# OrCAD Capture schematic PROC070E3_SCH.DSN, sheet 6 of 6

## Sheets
6 05. LCD_POWER: size C; title: LCD POWER
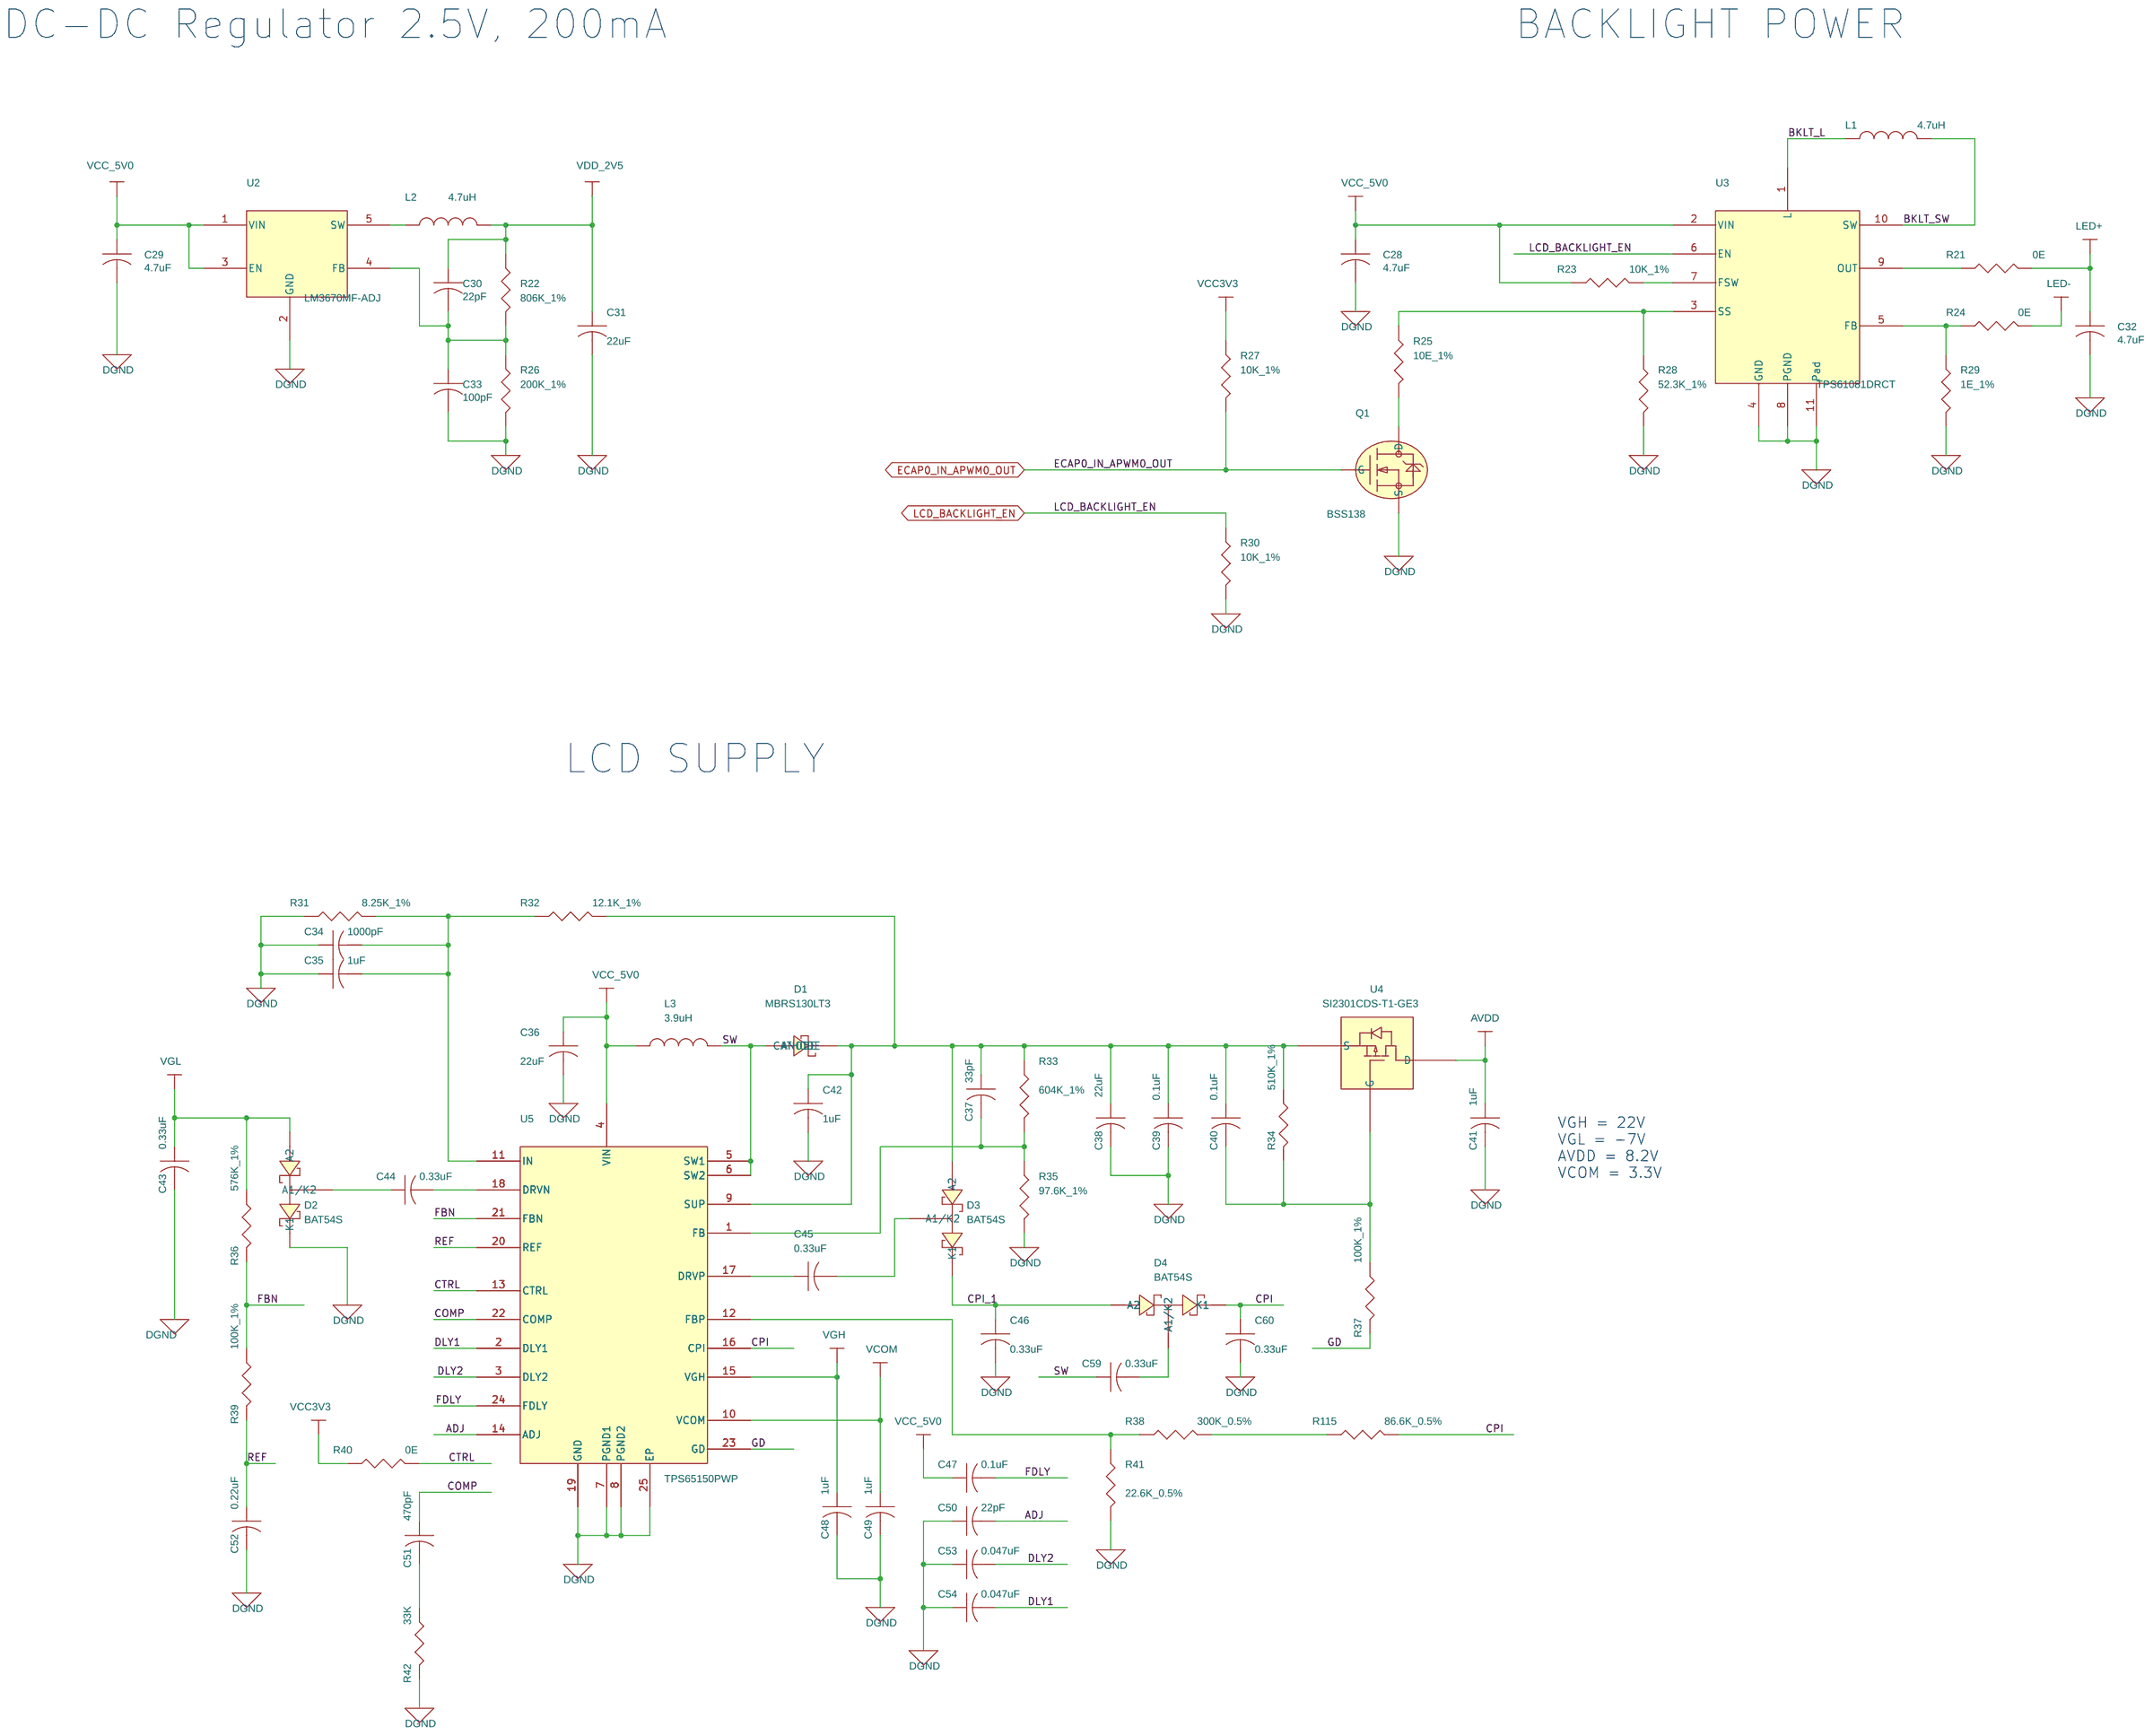
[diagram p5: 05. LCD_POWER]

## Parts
C28  4.7uF  [CAP0402_0-75]
C29  4.7uF  [CAP0402_0-75]
C30  22pF  [CAP0402_0-75]
C31  22uF  [CAP0805_1]
C32  4.7uF  [CAP0805_1-5]
C33  100pF  [CAP0402]
C34  1000pF  [CAP0402_0-75]
C35  1uF  [CAP0402_0-75]
C36  22uF  [CAP0805_1]
C37  33pF  [CAP0402]
C38  22uF  [CAP0805_1]
C39  0.1uF  [CAP0201_0-5]
C40  0.1uF  [CAP0201_0-5]
C41  1uF  [CAP0805_1-5]
C42  1uF  [CAP0805_1-5]
C43  0.33uF  [CAP0603]
C44  0.33uF  [CAP0603]
C45  0.33uF  [CAP0603]
C46  0.33uF  [CAP0603]
C47  0.1uF  [CAP0201_0-5]
C48  1uF  [CAP0805_1-5]
C49  1uF  [CAP0402_0-75]
C50  22pF  [CAP0402_0-75]
C51  470pF  [CAP0402_0-75]
C52  0.22uF  [CAP0603]
C53  0.047uF  [CAP0402]
C54  0.047uF  [CAP0402]
C59  0.33uF  [CAP0603]
C60  0.33uF  [CAP0603]
D1  MBRS130LT3  [DIO_SMB]
D2  BAT54S  [DIO_SOT23_123]
D3  BAT54S  [DIO_SOT23_123]
D4  BAT54S  [DIO_SOT23_123]
L1  4.7uH  [IND_VLCF5020T_205X210_SMD]
L2  4.7uH  [IND_LQH32PN_140X110_SMD_1-7]
L3  3.9uH  [IND_ELL4GG_170X170_SMD]
Q1  BSS138  [TO_SOT23-123]
R21  0E  [RES0402_0-5]
R22  806K_1%  [RES0402]
R23  10K_1%  [RES0402_0-5]
R24  0E  [RES0402_0-5]
R25  10E_1%  [RES0402_0-5]
R26  200K_1%  [RES0402]
R27  10K_1%  [RES0402_0-5]
R28  52.3K_1%  [RES0201_0-5]
R29  1E_1%  [RES0402]
R30  10K_1%  [RES0402_0-5]
R31  8.25K_1%  [RES0402]
R32  12.1K_1%  [RES0402]
R33  604K_1%  [RES0603]
R34  510K_1%  [RES0402]
R35  97.6K_1%  [RES0402_0-5]
R36  576K_1%  [RES0603]
R37  100K_1%  [RES0402_0-5]
R38  300K_0.5%  [RES0603_0-75]
R39  100K_1%  [RES0402_0-5]
R40  0E  [RES0402_0-5]
R41  22.6K_0.5%  [RES0603_0-75]
R42  33K  [RES0402]
R115  86.6K_0.5%  [RES0603_0-75]
U2  LM3670MF-ADJ  [SOT23-5_1-5]
U3  TPS61081DRCT  [SON10_19-68_125X125]
U4  SI2301CDS-T1-GE3  [SOT23-123]
U5  TPS65150PWP  [HTSSOP24_TPS65150_180X310_1-2]

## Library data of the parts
C28 C29 = CAP: CAP CERAMIC 4.7uF 10V 10% X5R 0402; Chkd/date: MANIRAJA/050517; Crtd /date: MANIRAJA/050517; Custom_Duty: 15%; Customs_HS_Code: 85322990; Distributor_name: DIGIKEY; Distributor_part_number: 311-3477-1-ND; Height: 0.65MM; Mfr_name: YAGEO AMERICA; Mfr_part_number: CC0402KRX5R6BB475; Mistral Part No: 120014080006-R; Package: 0402; Part_type: CAPACITORS\CERAMIC; Project: GOLDEN-I LITE; RoHS: RoHS; Temperature: -55°C+85°C; Tolerance: 10%; Voltage: 10V; Wattage: NA; Weight: NA; Datasheet: Y:\MIS_DATABASE\DATASHEETS\CAPACITORS\YACC-X5R.PDF
C30 C50 = CAP: CAP CERAMIC 22pF 25V 5% NP0 0402; Chkd/date: VASANTHA/060117; Crtd /date: MAZHAR/040505; Custom_Duty: 15%; Customs_HS_Code: 85322990; Distributor_name: DIGIKEY; Distributor_part_number: 478-6192-2-ND; Height: 0.56MM; Mfr_name: AVX CORPORATION; Mfr_part_number: 04023A220JAT2A; Mistral Part No: 120009030322-R; Package: 0402; Part_type: CAPACITORS\CERAMIC; Project: TELEMATICS-02; RoHS: RoHS; Temperature: -55°C+125°C; Tolerance: 5%; Voltage: 25V; Wattage: NA; Weight: 0.65mg; Datasheet: Y:\MIS_DATABASE\DATASHEETS\CAPACITORS\AVX_MLC.PDF
C31 C36 C38 = CAP: CAP CERAMIC 22uF 16V 20% X5R 0805; Chkd/date: VASANTHA/220218; Crtd /date: ALVY/220218; Custom_Duty: 15%; Customs_HS_Code: 85322990; Distributor_name: DIGIKEY; Distributor_part_number: 1276-6780-1-ND; Footprint Path: Y:\MIS_DATABASE\Library\ALTIUM_TOOL\PCB_FOOTPRINTS\Altium_Footprint_Lib.PcbLib; Height: 0.95MM; Library Path: Y:\MIS_DATABASE\Library\ALTIUM_TOOL\SCHEMATICS_PARTS\MS_DISCRETE_Library.schlib; Mfr_name: SAMSUNG ELECTRO MECHANIC; Mfr_part_number: CL21A226MOCLRNC; Mistral Part No: 120018020013-R; Package: 0805; Part_type: CAPACITORS\CERAMIC; Project: 820TABPOC_CB; RoHS: RoHS; Temperature: -55°C+85°C; Tolerance: 20%; Voltage: 16V; Wattage: NA; Weight: NA; Datasheet: Y:\MIS_DATABASE\DATASHEETS\CAPACITORS\CL_SERIES.PDF
C32 = CAP: CAP CERAMIC 4.7uF 50V 20% X5R 0805; Chkd/date: VASANTHA/200614; Crtd /date: MANIRAJA/210317; Custom_Duty: 15%; Customs_HS_Code: 85322990; Distributor_name: DIGIKEY; Distributor_part_number: 445-5981-1-ND; Height: 1.45MM; Mfr_name: TDK CORPORATION; Mfr_part_number: C2012X5R1H475M125AB; Mistral Part No: 120014060013-R; Package: 0805; Part_type: CAPACITORS\CERAMIC; Project: AEGIS_POM; RoHS: RoHS; Temperature: -55°C+85°C; Tolerance: 20%; Voltage: 50V; Wattage: NA; Weight: 5.5mg; Datasheet: Y:\MIS_DATABASE\DATASHEETS\CAPACITORS\C2012X5R.PDF
C33 = CAP: CAP CERAMIC 100pF 25V 10% NP0 0402; Chkd/date: NAVEED/070814; Crtd /date: VASANTHA/300714; Custom_Duty: 15%; Customs_HS_Code: 85322990; Distributor_name: DIGIKEY; Distributor_part_number: 399-7748-1-ND; Height: 0.55MM; Mfr_name: KEMET; Mfr_part_number: C0402C101K3GACTU; Mistral Part No: 120014070037-R; Package: 0402; Part_type: CAPACITORS\CERAMIC; Project: AEGIS_POM; RoHS: RoHS; Temperature: NA; Tolerance: 10%; Voltage: 25V; Wattage: NA; Weight: NA; Datasheet: Y:\MIS_DATABASE\DATASHEETS\CAPACITORS\KEMET-C08.PDF
C34 = CAP: CAP CERAMIC 1000pF 25V 10% X7R 0402; Chkd/date: VASANTHA/191216; Crtd /date: MAZHAR/050307; Custom_Duty: 15%; Customs_HS_Code: 85322990; Distributor_name: DIGIKEY; Distributor_part_number: 399-1031-1-ND; Height: 0.55MM; Mfr_name: KEMET; Mfr_part_number: C0402C102K3RACTU; Mistral Part No: 120009030145-R; Package: 0402; Part_type: CAPACITORS\CERAMIC; Project: LTS; RoHS: RoHS; Temperature: -55°C+125°C; Tolerance: 10%; Voltage: 25V; Wattage: NA; Weight: 0.65mg; Datasheet: Y:\MIS_DATABASE\DATASHEETS\CAPACITORS\KEMET-C08.PDF
C35 C49 = CAP: CAP CERAMIC 1uF 16V 10% X5R 0402; Chkd/date: MANIRAJA/210817; Crtd /date: MANIRAJA/210817; Custom_Duty: 15%; Customs_HS_Code: 85322990; Distributor_name: DIGIKEY; Distributor_part_number: 587-3709-1-ND; Height: 0.55MM; Mfr_name: TAIYO YUDEN; Mfr_part_number: EMK105BJ105KVHF; Mistral Part No: 120011050002-R; Package: 0402; Part_type: CAPACITORS\CERAMIC; Project: TI_RF_DC CARD; RoHS: RoHS; Temperature: -55°C+85°C; Tolerance: 10%; Voltage: 16V; Wattage: NA; Weight: 0.65mg; Datasheet: Y:\MIS_DATABASE\DATASHEETS\CAPACITORS\EMK105BJ105KVHF.PDF
C37 = CAP: CAP CERAMIC 33pF 16V 1% NP0 0402; Chkd/date: MAZHAR/241208; Crtd /date: USMAN/150908; Custom_Duty: 15%; Customs_HS_Code: 85322990; Distributor_name: DIGIKEY; Distributor_part_number: 0402YA330FAT2A-ND; Height: 0.60MM; Mfr_name: AVX CORPORATION; Mfr_part_number: 0402YA330FAT2A; Mistral Part No: 120009030388-R; Package: 0402; Part_type: CAPACITORS\CERAMIC; Project: MDC; RoHS: RoHS; Tolerance: 1%; Voltage: 16V; Datasheet: Y:\MIS_DATABASE\DATASHEETS\CAPACITORS\AVX_MLC.PDF
C39 C40 C47 = CAP: CAP CERAMIC 0.1uF 16V 10% X5R 0201; Chkd/date: VASANTHA/140217; Crtd /date: MANIRAJA/140217; Custom_Duty: 15%; Customs_HS_Code: 85322990; Distributor_name: DIGIKEY; Distributor_part_number: 311-1597-1-ND; Height: 0.33MM; Mfr_name: YAGEO AMERICA; Mfr_part_number: CC0201KRX5R7BB104; Mistral Part No: 120009030072-R; Package: 0201; Part_type: CAPACITORS\CERAMIC; Project: GOLDEN-I LITE; RoHS: RoHS; Temperature: -55°C+85°C; Tolerance: 10%; Voltage: 16V; Wattage: NA; Weight: 0.17mg; Datasheet: Y:\MIS_DATABASE\DATASHEETS\CAPACITORS\CC-SERIES.PDF
C41 C42 C48 = CAP: CAP CERAMIC 1uF 50V 10% X7R 0805; Chkd/date: MANIRAJA/130617; Crtd /date: MAZHAR/190111; Custom_Duty: 15%; Customs_HS_Code: 85322990; Distributor_name: DIGIKEY; Distributor_part_number: 490-4736-1-ND; Height: 1.35MM; Mfr_name: MURATA; Mfr_part_number: GRM21BR71H105KA12L; Mistral Part No: 120011010018-R; Package: 0805; Part_type: CAPACITORS\CERAMIC; Project: ITS-PWR_CARD; RoHS: RoHS; Temperature: -55°C+125°C; Tolerance: 10%; Voltage: 50V; Wattage: NA; Weight: 6mg; Datasheet: Y:\MIS_DATABASE\DATASHEETS\CAPACITORS\GRM21BR71H105KA12.PDF
C43-C46 C59 C60 = CAP: CAP CERAMIC 0.33uF 50V 20% X5R 0603; Chkd/date: BAVISH/111011; Crtd /date: CHAITHANYA/111011; Custom_Duty: 15%; Customs_HS_Code: 85322990; Distributor_name: DIGIKEY; Distributor_part_number: 445-7463-1-ND; Height: 0.90MM; Mfr_name: TDK CORPORATION; Mfr_part_number: C1608X5R1H334M; Mistral Part No: 120011100028-R; Package: 0603; Part_type: CAPACITORS\CERAMIC; Project: VIDEO-GADGET; RoHS: RoHS; Temperature: -55°C+85°C; Tolerance: 20%; Voltage: 50V; Wattage: NA; Weight: NA; Datasheet: Y:\MIS_DATABASE\DATASHEETS\CAPACITORS\TDK_CAP.PDF
C51 = CAP: CAP CERAMIC 470pF 25V 10% X7R 0402; Chkd/date: VASANTHA/281216; Crtd /date: CHAITHANYA/071111; Custom_Duty: 15%; Customs_HS_Code: 85322990; Distributor_name: DIGIKEY; Distributor_part_number: PCC471BQCT-ND; Height: 0.55MM; Mfr_name: PANASONIC-ECG; Mfr_part_number: ECJ-0EB1E471K; Mistral Part No: 120011110003-R; Package: 0402; Part_type: CAPACITORS\CERAMIC; Project: NA10NG; RoHS: RoHS; Temperature: -55°C+125°C; Tolerance: 10%; Voltage: 25V; Wattage: NA; Weight: 0.8mg; Datasheet: Y:\MIS_DATABASE\DATASHEETS\CAPACITORS\PAN-ECJ.PDF
C52 = CAP: CAP CERAMIC 0.22uF 25V 10% X7R 0603; Chkd/date: MAZHAR/291110; Crtd /date: BAVISH/291110; Custom_Duty: 15%; Customs_HS_Code: 85322990; Distributor_name: DIGIKEY; Distributor_part_number: 445-5191-1-ND; Height: 0.90MM; Mfr_name: TDK CORPORATION; Mfr_part_number: C1608X7R1E224K; Mistral Part No: 120010110026-R; Package: 0603; Part_type: CAPACITORS\CERAMIC; Project: EM-FLS; RoHS: RoHS; Temperature: -55°C+125°C; Tolerance: 5%; Voltage: 25V; Wattage: NA; Weight: NA; Datasheet: Y:\MIS_DATABASE\DATASHEETS\CAPACITORS\C1608.PDF
C53 C54 = CAP: CAP CERAMIC 0.047uF 25V 10% X7R 0402; Chkd/date: MAZHAR/041208; Crtd /date: USMAN/011208; Custom_Duty: 15%; Customs_HS_Code: 85322990; Distributor_name: DIGIKEY; Distributor_part_number: 490-3254-1-ND; Height: 0.55MM; Mfr_name: MURATA; Mfr_part_number: GRM155R71E473KA88D; Mistral Part No: 120009030046; Package: 0402; Part_type: CAPACITORS\CERAMIC; Project: PICO PROJECTOR; Tolerance: 10%; Voltage: 25V; Datasheet: Y:\MIS_DATABASE\DATASHEETS\CAPACITORS\GRM188SERIES.PDF
D1 = DIODE_SCHOTTKY: DIODE SCHOTTKY 30V 1A SMB; Alternate_mfr_name_A: ON SEMICONDUCTOR; Alternate_mfr_part_number_A: MBRS130LT3G; Chkd/date: SHREESHAIL/191205; Crtd /date: MAZHAR/020505; Custom_Duty: 15%; Customs_HS_Code: 85412900; Distributor_name: DIGIKEY; Distributor_part_number: MBRS130LT3OSCT-ND; Height: 2.56MM; Mfr_name: ON SEMICONDUCTOR; Mistral Part No: 130009030214; Package: SMB; Part_type: DIODE\SCHOTTKY; Project: HSWD; Voltage: 30V; Datasheet: Y:\MIS_DATABASE\DATASHEETS\DISCRETES\DIODES\MBRS130LT3-D.PDF
D2-D4 = DIODE_BAT54S_SOT23-123: DIODE SCHOTTKY 30V 200mA SOT23-3; Chkd/date: SHREESHAIL/191205; Crtd /date: MAZHAR/270405; Custom_Duty: 15%; Customs_HS_Code: 85412900; Distributor_name: DIGIKEY; Distributor_part_number: BAT54SFSCT-ND; Height: 1.15MM; Mfr_name: FAIRCHILD; Mistral Part No: 130009030192; Package: SOT23-3; Part_type: DIODE\SCHOTTKY; Project: RAINIER-3; Voltage: 30V; Datasheet: Y:\MIS_DATABASE\DATASHEETS\DISCRETES\DIODES\BAT54C.PDF
L1 = INDUCTOR: IND POWER 4.7uH 1.7A 30% SMD; Chkd/date: VASANTHA/230714; Crtd /date: BAVISH/120511; Custom_Duty: 24%; Customs_HS_Code: 85437099; Distributor_name: DIGIKEY; Distributor_part_number: 445-3207-1-ND; Height: 2.00MM; Mfr_name: TDK CORPORATION; Mfr_part_number: VLCF5020T-4R7N1R7-1; Mistral Part No: 130011050012-R; Package: SMD; Project: CENTAURUS_LCD-ADAPTER; RoHS: RoHS; Temperature: -40°C+105°C; Tolerance: 30%; Voltage: NA; Wattage: NA; Weight: NA; Datasheet: Y:\MIS_DATABASE\DATASHEETS\DISCRETES\INDUCTORS\VLCF5020T.PDF
L2 = INDUCTOR: IND POWER 4.7uH 1000mA 30% SMD; Chkd/date: MANIRAJA/300517; Crtd /date: MUDDU/080310; Custom_Duty: 24%; Customs_HS_Code: 85437099; Distributor_name: DIGIKEY; Distributor_part_number: 490-5338-1-ND; Height: 1.70MM; Mfr_name: MURATA; Mfr_part_number: LQH32PN4R7NN0L; Mistral Part No: 130010030011-R; Package: SMD; Project: VME_DSP_SUITE; RoHS: RoHS; Temperature: -40°C+85°C; Tolerance: 30%; Voltage: NA; Wattage: NA; Weight: NA; Datasheet: Y:\MIS_DATABASE\DATASHEETS\DISCRETES\INDUCTORS\LQH32PN.PDF
L3 = INDUCTOR: IND CHOKE 3.9uH 30% SMD; Chkd/date: VASANTHA/170215; Crtd /date: JEBRAN/160115; Custom_Duty: 24%; Customs_HS_Code: 85437099; Distributor_name: DIGIKEY; Distributor_part_number: PCD2201CT-ND; Height: 1.40MM; Mfr_name: PANASONIC; Mfr_part_number: ELL-4GG3R9N; Mistral Part No: 130015010034-R; Package: SMD; Project: ZK BIOMETRIC; RoHS: RoHS; Temperature: -40°C+85°C; Tolerance: 30%; Voltage: NA; Wattage: NA; Weight: NA; Datasheet: Y:\MIS_DATABASE\DATASHEETS\DISCRETES\INDUCTORS\ELL4GG.PDF
Q1 = MOSFET_BSS138: IC MOSFET N-CHANNEL 50V 200mA SOT23-3; Chkd/date: SUHAS/191010; Crtd /date: USMAN/240709; Custom_Duty: 15%; Customs_HS_Code: 85423100; Distributor_name: DIGIKEY; Distributor_part_number: BSS138CT-ND; Height: 1.20MM; Mfr_name: DIODES INC; Mfr_part_number: BSS138-7-F; Mistral Part No: 142009070019-R; Package: SOT23-3; Part_type: ICS\POWER\MOSFET; Project: KHAN_MAIN; RoHS: RoHS; Temperature: -55°C+150°C; Voltage: 50V; Wattage: 300mW; Weight: 0.008g; Datasheet: Y:\MIS_DATABASE\DATASHEETS\DISCRETES\TRANSISTORS_FETS\BSS138.PDF
R21 R24 R40 = RESISTOR: RES 0E 1/16W 0402; Chkd/date: VASANTHA/201216; Crtd /date: MUDDU/190810; Custom_Duty: 15%; Customs_HS_Code: 85332119; Distributor_name: DIGIKEY; Distributor_part_number: 541-0.0JCT-ND; Footprint Path: Y:\MIS_DATABASE\Library\ALTIUM_TOOL\PCB_FOOTPRINTS\Altium_Footprint_Lib.PcbLib; Height: 0.40MM; Library Path: Y:\MIS_DATABASE\Library\ALTIUM_TOOL\SCHEMATICS_PARTS\MS_DISCRETE_Library.schlib; Mfr_name: VISHAY; Mfr_part_number: CRCW04020000Z0ED; Mistral Part No: 110010080019-P; Package: 0402; Part_type: RESISTORS\FIXED; Project: PB_BUGBASE; RoHS: Pb-Free; Temperature: -55°C+155°C; Tolerance: NA; Voltage: NA; Wattage: 1/16W; Weight: 0.65g/1000pcs; Datasheet: Y:\MIS_DATABASE\DATASHEETS\RESISTORS\CRCW0603.PDF
R22 = RESISTOR: RES 806K 1/16W 1% 0402; Chkd/date: MAZHAR/150709; Crtd /date: USMAN/140409; Custom_Duty: 15%; Customs_HS_Code: 85332119; Distributor_name: DIGIKEY; Distributor_part_number: P806KLCT-ND; Height: 0.40MM; Mfr_name: PANASONIC-ECG; Mfr_part_number: ERJ-2RKF8063X; Mistral Part No: 110009050012-R; Package: 0402; Part_type: RESISTORS\FIXED; Project: AARDK; RoHS: RoHS; Tolerance: 1%; Wattage: 1/16W; Datasheet: Y:\MIS_DATABASE\DATASHEETS\RESISTORS\PAN-ERJSERIES.PDF
R23 R27 R30 = RESISTOR: RES 10K 1/10W 1% 0402; Chkd/date: MANIRAJA/190218; Crtd /date: NAVEED/280515; Custom_Duty: 15%; Customs_HS_Code: 85332119; Distributor_name: DIGIKEY; Distributor_part_number: P10.0KLCT-ND; Footprint Path: Y:\MIS_DATABASE\Library\ALTIUM_TOOL\PCB_FOOTPRINTS\Altium_Footprint_Lib.PcbLib; Height: 0.40MM; Library Path: Y:\MIS_DATABASE\Library\ALTIUM_TOOL\SCHEMATICS_PARTS\MS_DISCRETE_Library.schlib; Mfr_name: PANASONIC-ECG; Mfr_part_number: ERJ-2RKF1002X; Mistral Part No: 110015050015-R; Package: 0402; Part_type: RESISTORS\FIXED; Project: DLRL NARROW BAND; RoHS: RoHS; Temperature: -55°C+155°C; Tolerance: 1%; Voltage: NA; Wattage: 1/10W; Weight: 0.8mg; Datasheet: Y:\MIS_DATABASE\DATASHEETS\RESISTORS\PAN-ERJSER_NOV17.PDF
R25 = RESISTOR: RES 10E 1/10W 1% 0402; Chkd/date: VASANTHA/201216; Crtd /date: MAZHAR/120505; Custom_Duty: 15%; Customs_HS_Code: 85332119; Distributor_name: DIGIKEY; Distributor_part_number: P10.0LCT-ND; Footprint Path: Y:\MIS_DATABASE\Library\ALTIUM_TOOL\PCB_FOOTPRINTS\Altium_Footprint_Lib.PcbLib; Height: 0.40MM; Library Path: Y:\MIS_DATABASE\Library\ALTIUM_TOOL\SCHEMATICS_PARTS\MS_DISCRETE_Library.schlib; Mfr_name: PANASONIC-ECG; Mfr_part_number: ERJ-2RKF10R0X; Mistral Part No: 110009030203-R; Package: 0402; Part_type: RESISTORS\FIXED; Project: CTP02_REVA_BASE; RoHS: RoHS; Temperature: -55°C+155°C; Tolerance: 1%; Voltage: NA; Wattage: 1/10W; Weight: 0.8mg; Datasheet: Y:\MIS_DATABASE\DATASHEETS\RESISTORS\PAN-ERJSER_NOV17.PDF
R26 = RESISTOR: RES 200K 1/16W 1% 0402; Chkd/date: SHREESHAIL/121205; Crtd /date: MAZHAR/010805; Custom_Duty: 15%; Customs_HS_Code: 85332119; Distributor_name: DIGIKEY; Distributor_part_number: P200KLCT-ND; Footprint Path: Y:\MIS_DATABASE\Library\ALTIUM_TOOL\PCB_FOOTPRINTS\Altium_Footprint_Lib.PcbLib; Height: 0.40MM; Library Path: Y:\MIS_DATABASE\Library\ALTIUM_TOOL\SCHEMATICS_PARTS\MS_DISCRETE_Library.schlib; Mfr_name: PANASONIC-ECG; Mfr_part_number: ERJ-2RKF2003X; Mistral Part No: 110009030474-R; Package: 0402; Part_type: RESISTORS\FIXED; Project: PMP-VIOMEDIA; RoHS: RoHS; Tolerance: 1%; Wattage: 1/16W; Datasheet: Y:\MIS_DATABASE\DATASHEETS\RESISTORS\ERJ-2R.PDF
R28 = RESISTOR: RES 52.3K 1/20W 1% 0201; Chkd/date: MANIRAJA/050517; Crtd /date: MANIRAJA/050517; Custom_Duty: 15%; Customs_HS_Code: 85332119; Distributor_name: DIGIKEY; Distributor_part_number: YAG2718CT-ND; Height: 0.26MM; Mfr_name: YAGEO AMERICA; Mfr_part_number: RC0201FR-0752K3L; Mistral Part No: 110009030972-R; Package: 0201; Part_type: RESISTORS\FIXED; Project: GOLDEN-I LITE; RoHS: RoHS; Temperature: -55°C+125°C; Tolerance: 1%; Voltage: NA; Wattage: 1/20W; Weight: NA; Datasheet: Y:\MIS_DATABASE\DATASHEETS\RESISTORS\RC0201.PDF
R29 = RESISTOR: RES 1E 1/16W 1% 0402; Alternate_mfr_name_D: ROHM; Alternate_mfr_part_number_D: MCR01MZPFL1R00; Chkd/date: SHREESHAIL/190406; Crtd /date: MAZHAR/130306; Custom_Duty: 15%; Customs_HS_Code: 85332119; Distributor_name: DIGIKEY; Distributor_name_D: DIGIKEY; Distributor_part_number: 311-1.00LRCT-ND; Distributor_part_number_D: RHM1.00LCT-ND; Height: 0.40MM; Mfr_name: YAGEO AMERICA; Mfr_part_number: RC0402FR-071RL; Mistral Part No: 110009030394; Package: 0402; Part_type: RESISTORS\FIXED; Project: J32; Tolerance: 1%; Wattage: 1/16W; Datasheet: Y:\MIS_DATABASE\DATASHEETS\RESISTORS\YAGEO_RES.PDF
R31 = RESISTOR: RES 8.25K 1/8W 1% 0402; Chkd/date: MAZHAR/150711; Crtd /date: BAVISH/230611; Custom_Duty: 15%; Customs_HS_Code: 85332119; Distributor_name: DIGIKEY; Distributor_part_number: CRCW04028K25FKEDHP-ND; Height: 0.40MM; Mfr_name: VISHAY; Mfr_part_number: CRCW04028K25FKEDHP; Mistral Part No: 110011060045-R; Package: 0402; Part_type: RESISTORS\FIXED; Project: HMC; RoHS: RoHS; Temperature: -55°C+155°C; Tolerance: 1%; Voltage: NA; Wattage: 1/8W; Weight: 0.65mg; Datasheet: Y:\MIS_DATABASE\DATASHEETS\RESISTORS\CRCW0402-HP.PDF
R32 = RESISTOR: RES 12.1K 1/16W 1% 0402; Chkd/date: VASANTHA/010714; Crtd /date: VASANTHA/010714; Custom_Duty: 15%; Customs_HS_Code: 85412900; Distributor_name: DIGIKEY; Distributor_part_number: 311-12.1KLRCT-ND; Footprint Path: Y:\MIS_DATABASE\Library\ALTIUM_TOOL\PCB_FOOTPRINTS\Altium_Footprint_Lib.PcbLib; Height: 0.40MM; Library Path: Y:\MIS_DATABASE\Library\ALTIUM_TOOL\SCHEMATICS_PARTS\MS_DISCRETE_Library.schlib; Mfr_name: YAGEO AMERICA; Mfr_part_number: RC0402FR-0712K1L; Mistral Part No: 110014070001-R; Package: 0402; Part_type: RESISTORS\FIXED; Project: AEGIS_POM; RoHS: RoHS; Temperature: -55°C +155°C; Tolerance: 1%; Voltage: NA; Wattage: 1/16W; Weight: 0.65mg; Datasheet: Y:\MIS_DATABASE\DATASHEETS\RESISTORS\YAGEO-RC0402.PDF
R33 = RESISTOR: RES 604K 1/10W 1% 0603; Alternate_mfr_name_A: PANASONIC-ECG; Alternate_mfr_part_number_A: ERJ-3EKF6043V; Chkd/date: SUHAS/060411; Crtd /date: MUDDU/240210; Custom_Duty: 15%; Customs_HS_Code: 85332119; Distributor_name: DIGIKEY; Distributor_name_A: DIGIKEY; Distributor_part_number: 541-604KHCT-ND; Distributor_part_number_A: P604KHCT-ND; Height: 0.55MM; Mfr_name: VISHAY; Mfr_part_number: CRCW0603604KFKEA; Mistral Part No: 110010020037-R; Package: 0603; Part_type: RESISTORS\FIXED; Project: NPOL_PREAMP; RoHS: Pb-Free; Temperature: -55°C+125°C; Tolerance: 1%; Wattage: 1/10W; Weight: NA; Datasheet: Y:\MIS_DATABASE\DATASHEETS\RESISTORS\CRCW.PDF
R34 = RESISTOR: RES 510K 1/16W 1% 0402; Chkd/date: VASANTHA/210814; Crtd /date: USMAN/260313; Custom_Duty: 15%; Customs_HS_Code: 85332119; Distributor_name: DIGIKEY; Distributor_part_number: 541-510KLCT-ND; Height: 0.40MM; Mfr_name: VISHAY; Mfr_part_number: CRCW0402510KFKED; Mistral Part No: 110013030019-R; Package: 0402; Part_type: RESISTORS\FIXED; Project: GEN_3-8; RoHS: RoHS; Temperature: -55°C+155°C; Tolerance: 1%; Voltage: NA; Wattage: 1/16W; Weight: 0.65mg; Datasheet: Y:\MIS_DATABASE\DATASHEETS\RESISTORS\CRCW0603.PDF
R35 = RESISTOR: RES 97.6K 1/10W 1% 0402; Chkd/date: MANIRAJA/250118; Crtd /date: MANIRAJA/250118; Custom_Duty: 15%; Customs_HS_Code: 85332119; Distributor_name: DIGIKEY; Distributor_part_number: P97.6KLCT-ND; Footprint Path: Y:\MIS_DATABASE\Library\ALTIUM_TOOL\PCB_FOOTPRINTS\Altium_Footprint_Lib.PcbLib; Height: 0.40MM; Library Path: Y:\MIS_DATABASE\Library\ALTIUM_TOOL\SCHEMATICS_PARTS\MS_DISCRETE_Library.schlib; Mfr_name: PANASONIC-ECG; Mfr_part_number: ERJ-2RKF9762X; Mistral Part No: 110018010019-R; Package: 0402; Part_type: RESISTORS\FIXED; Project: TI_SVB_MAXWELL_LCD-AB; RoHS: RoHS; Temperature: -55°C+155°C; Tolerance: 1%; Voltage: NA; Wattage: 1/10W; Weight: 0.8mg; Datasheet: Y:\MIS_DATABASE\DATASHEETS\RESISTORS\PAN-ERJSER_NOV17.PDF
R36 = RESISTOR: RES 576K 1/10W 1% 0603; Chkd/date: BAVISH/111011; Crtd /date: CHAITHANYA/111011; Custom_Duty: 15%; Customs_HS_Code: 85332119; Distributor_name: DIGIKEY; Distributor_part_number: 311-576KHRCT-ND; Height: 0.55MM; Mfr_name: YAGEO; Mfr_part_number: RC0603FR-07576KL; Mistral Part No: 110011100016-R; Package: 0603; Part_type: RESISTORS\FIXED; Project: VIDEO-GADGET; RoHS: RoHS; Temperature: -55°C+155°C; Tolerance: 1%; Voltage: NA; Wattage: 1/10W; Weight: NA; Datasheet: Y:\MIS_DATABASE\DATASHEETS\RESISTORS\RC0603.PDF
R37 R39 = RESISTOR: RES 100K 1/16W 1% 0402; Chkd/date: MANIRAJA/110917; Crtd /date: MANIRAJA/110917; Custom_Duty: 15%; Customs_HS_Code: 85332119; Distributor_name: DIGIKEY; Distributor_part_number: 311-100KLRCT-ND; Height: 0.40MM; Mfr_name: YAGEO AMERICA; Mfr_part_number: RC0402FR-07100KL; Mistral Part No: 110009030187-R; Package: 0402; Part_type: RESISTORS\FIXED; Project: CRADE RF CARD; RoHS: RoHS; Temperature: -55°C+155°C; Tolerance: 1%; Voltage: NA; Wattage: 1/16W; Weight: 0.65mg; Datasheet: Y:\MIS_DATABASE\DATASHEETS\RESISTORS\YAGEO-RC0402.PDF
R38 = RESISTOR: RES 300K 1/10W 0.5% 0603; Chkd/date: MANIRAJA/220318; Crtd /date: MANIRAJA/220318; Custom_Duty: 15%; Customs_HS_Code: 85332119; Distributor_name: DIGIKEY; Distributor_part_number: 311-300KDCT-ND; Footprint Path: Y:\MIS_DATABASE\Library\ALTIUM_TOOL\PCB_FOOTPRINTS\Altium_Footprint_Lib.PcbLib; Height: 0.55MM; Library Path: Y:\MIS_DATABASE\Library\ALTIUM_TOOL\SCHEMATICS_PARTS\MS_DISCRETE_Library.schlib; Mfr_name: YAGEO AMERICA; Mfr_part_number: RT0603DRD07300KL; Mistral Part No: 110018030013-R; Package: 0603; Part_type: RESISTORS\FIXED; Project: TI_SVB_MAXWELL_LCD-AB; RoHS: RoHS; Temperature: -55°C+125°C; Tolerance: 0.5%; Voltage: NA; Wattage: 1/10W; Weight: 2mg; Datasheet: Y:\MIS_DATABASE\DATASHEETS\RESISTORS\RT_SER.PDF
R41 = RESISTOR: RES 22.6K 1/10W 0.5% 0603; Chkd/date: MANIRAJA/220318; Crtd /date: MANIRAJA/220318; Custom_Duty: 15%; Customs_HS_Code: 85332119; Distributor_name: DIGIKEY; Distributor_part_number: 311-2487-1-ND; Footprint Path: Y:\MIS_DATABASE\Library\ALTIUM_TOOL\PCB_FOOTPRINTS\Altium_Footprint_Lib.PcbLib; Height: 0.55MM; Library Path: Y:\MIS_DATABASE\Library\ALTIUM_TOOL\SCHEMATICS_PARTS\MS_DISCRETE_Library.schlib; Mfr_name: YAGEO AMERICA; Mfr_part_number: RT0603DRE0722K6L; Mistral Part No: 110018030012-R; Package: 0603; Part_type: RESISTORS\FIXED; Project: TI_SVB_MAXWELL_LCD-AB; RoHS: RoHS; Temperature: -55°C+125°C; Tolerance: 0.5%; Voltage: NA; Wattage: 1/10W; Weight: 2mg; Datasheet: Y:\MIS_DATABASE\DATASHEETS\RESISTORS\RT_SER.PDF
R42 = RESISTOR: RES 33K 1/16W 5% 0402; Alternate_mfr_name_A: STACKPOLE ELECTRONICS; Alternate_mfr_part_number_A: RMCF0402JT33R0; Chkd/date: VASANTHA/011015; Crtd /date: BAVISH/270411; Custom_Duty: 15%; Customs_HS_Code: 85332119; Distributor_name: DIGIKEY; Distributor_name_A: DIGIKEY; Distributor_part_number: 311-33KJRCT-ND; Distributor_part_number_A: RMCF0402JT33R0CT-ND; Height: 0.40MM; Mfr_name: YAGEO AMERICA; Mfr_part_number: RC0402JR-0733KL; Mistral Part No: 110011040032-R; Package: 0402; Part_type: RESISTORS\FIXED; Project: OMAPL1_PEC20; RoHS: RoHS; Temperature: -55°C+155°C; Tolerance: 5%; Voltage: NA; Wattage: 1/16W; Weight: NA; Datasheet: Y:\MIS_DATABASE\DATASHEETS\RESISTORS\YAGEO_RC0402JR.PDF
R115 = RESISTOR: RES 86.6K 1/10W 0.5% 0603; Chkd/date: MANIRAJA/220318; Crtd /date: MANIRAJA/220318; Custom_Duty: 15%; Customs_HS_Code: 85332119; Distributor_name: DIGIKEY; Distributor_part_number: 311-2390-1-ND; Footprint Path: Y:\MIS_DATABASE\Library\ALTIUM_TOOL\PCB_FOOTPRINTS\Altium_Footprint_Lib.PcbLib; Height: 0.55MM; Library Path: Y:\MIS_DATABASE\Library\ALTIUM_TOOL\SCHEMATICS_PARTS\MS_DISCRETE_Library.schlib; Mfr_name: YAGEO AMERICA; Mfr_part_number: RT0603DRD0786K6L; Mistral Part No: 110018030014-R; Package: 0603; Part_type: RESISTORS\FIXED; Project: TI_SVB_MAXWELL_LCD-AB; RoHS: RoHS; Temperature: -55°C+125°C; Tolerance: 0.5%; Voltage: NA; Wattage: 1/10W; Weight: 2mg; Datasheet: Y:\MIS_DATABASE\DATASHEETS\RESISTORS\RT_SER.PDF
U2 = LM3670MF-ADJ_SOT23-5: IC ADJ MINIATURE STEP DOWN DC TO DC CONVERTER SOT23-5; Chkd/date: MANIRAJA/250118; Crtd /date: MANIRAJA/250118; Custom_Duty: 15%; Customs_HS_Code: 85423100; Distributor_name: DIGIKEY; Distributor_part_number: LM3670MF-ADJ/NOPBCT-ND; Height: 1.45MM; Mfr_name: TEXAS INSTRUMENTS; Mfr_part_number: LM3670MF-ADJ/NOPB; Mistral Part No: 142018010013-R; Package: SOT23-5; Part_type: ICS\POWER\DC-DC CONVERTER; Project: TI_SVB_MAXWELL_LCD-AB; RoHS: RoHS; Temperature: -40°C+85°C; Tolerance: NA; Voltage: NA; Wattage: NA; Weight: 6.3mg; Datasheet: Y:\MIS_DATABASE\DATASHEETS\ICS\POWER\LM3670XX.PDF
U3 = TPS61081DRCT_SON10: IC STEP-UP 1.3A DC/DC CONVERTER SON10; Chkd/date: SUHAS/211010; Crtd /date: MAZHAR/121009; Custom_Duty: 15%; Customs_HS_Code: 85423100; Distributor_name: DIGIKEY; Distributor_part_number: 296-21556-1-ND; Height: 1.00MM; Mfr_name: TEXAS INSTRUMENTS; Mistral Part No: 142009100003; Package: SON10; Part_type: ICS\POWER\DC-DC CONVERTER; Project: GEACOM_PHRAZER; RoHS: Sb/ Br FREE; Temperature: -40°C+85°C; Datasheet: Y:\MIS_DATABASE\DATASHEETS\ICS\POWER\TPS61081.PDF
U4 = SI2301CDS_SOT23-3: MOSFET P-CHANNEL 20V 3.1A SOT23-3; Chkd/date: SUHAS/141010; Crtd /date: MUDDU/170310; Custom_Duty: 15%; Customs_HS_Code: 85412900; Distributor_name: DIGIKEY; Distributor_part_number: SI2301CDS-T1-GE3CT-ND; Height: 1.10MM; Mfr_name: VISHAY; Mistral Part No: 130010030027-P; Package: SOT23-3; Part_type: TRANSISTOR\MOSFET; Project: THERADOME; RoHS: Pb-Free; Temperature: -55°C+150°C; Weight: NA; Datasheet: Y:\MIS_DATABASE\DATASHEETS\DISCRETES\TRANSISTORS_FETS\SI2301CDS-T1-GE3.PDF
U5 = TPS65150PWP_TSSOP24: IC LOW INPUT VOLTAGE COMPACT LCD BIAS WITH  VCOM BUFFER HTSSOP24; Chkd/date: MANIRAJA/281117; Crtd /date: CHAITHANYA/24/09/11; Custom_Duty: 15%; Customs_HS_Code: 85423100; Distributor_name: DIGIKEY; Distributor_part_number: TPS65150PWP-ND; Height: 1.20MM; Mfr_name: TEXAS INSTRUMENTS; Mistral Part No: 142011090022-R; Package: HTSSOP24; Part_type: ICS\POWER\MANAGEMENT; Project: AVCDP1; RoHS: RoHS; Temperature: -40°C+85°C; Tolerance: NA; Voltage: NA; Wattage: NA; Weight: NA; Datasheet: Y:\MIS_DATABASE\DATASHEETS\ICS\POWER\TPS65150PWP.PDF

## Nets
AVDD: C41.1 U4.3(D) ; also on sheet 5
DGND: C28.2 C29.2 C31.2 C32.2 C33.2 C34.1 C35.1 C36.2 C38.2 C39.2 C41.2 C42.2 C43.2 C46.2 C48.2 C49.2 C50.1 C52.2 C53.1 C54.1 C60.2 D2.2(K1) Q1.2(S) R26.2 R28.2 R29.2 R30.2 R31.1 R35.2 R41.2 R42.2 U2.2(GND) U3.4(GND) U3.8(PGND) U3.11(Pad) U5.7(PGND1) U5.8(PGND2) U5.19(GND) U5.25(EP) ; also on sheet 5
VCC3V3: R27.1 R40.1 ; also on sheet 5
VCC_5V0: C28.1 C29.1 C36.1 C47.1 L3.1 R23.1 U2.1(VIN) U2.3(EN) U3.2(VIN) U5.4(VIN) ; also on sheet 5
VDD_2V5: C30.1 C31.1 L2.2 R22.1 ; also on sheet 5
ADJ: C50.2 U5.14(ADJ)
BKLT_L: L1.1 U3.1(L)
BKLT_SW: L1.2 U3.10(SW)
COMP: C51.1 U5.22(COMP)
CPI: C60.1 D4.2(K1) R115.2 U5.16(CPI)
CPI_1: C46.1 D3.2(K1) D4.1(A2)
CTRL: R40.2 U5.13(CTRL)
DLY1: C54.2 U5.2(DLY1)
DLY2: C53.2 U5.3(DLY2)
ECAP0_IN_APWM0_OUT: Q1.1(G) R27.2 ; also on sheet 5
FBN: R36.2 R39.1 U5.21(FBN)
FDLY: C47.2 U5.24(FDLY)
GD: R37.2 U5.23(GD)
LCD_BACKLIGHT_EN: R30.1 U3.6(EN) ; also on sheet 5
LED+: C32.1 R21.2 ; also on sheet 5
LED-: R24.2 ; also on sheet 5
REF: C52.1 R39.2 U5.20(REF)
SW: C59.1 D1.2(ANODE) L3.2 U5.5(SW1) U5.6(SW2)
VCOM: C49.1 U5.10(VCOM) ; also on sheet 5
VGH: C48.1 U5.15(VGH) ; also on sheet 5
VGL: C43.1 D2.1(A2) R36.1 ; also on sheet 5
N18700915: R21.1 U3.9(OUT)
N18700972: R24.1 R29.1 U3.5(FB)
N18700978: R25.1 R28.1 U3.3(SS)
N18701008: Q1.3(D) R25.2
N18701075: R23.2 U3.7(FSW)
N18704134: C37.1 C38.1 C39.1 C40.1 C42.1 D1.1(CATHODE) D3.1(A2) R32.2 R33.1 R34.1 U4.2(S) U5.9(SUP)
N18704138: C40.2 R34.2 R37.1 U4.1(G)
N18704166: C37.2 R33.2 R35.1 U5.1(FB)
N18704218: C44.1 D2.3(A1/K2)
N18704228: C45.2 D3.3(A1/K2)
N18704232: R38.1 R41.1 U5.12(FBP)
N18704253: C44.2 U5.18(DRVN)
N18704306: C34.2 C35.2 R31.2 R32.1 U5.11(IN)
N18704451: C45.1 U5.17(DRVP)
N18706570: C51.2 R42.1
N18754754: L2.1 U2.5(SW)
N18754783: C30.2 C33.1 R22.2 R26.1 U2.4(FB)
N18857919: R38.2 R115.1
N18858160: C59.2 D4.3(A1/K2)

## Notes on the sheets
sheet 6
- DC-DC Regulator 2.5V, 200mA
- BACKLIGHT POWER
- LCD SUPPLY
- VGH = 22V
  VGL = -7V
  AVDD = 8.2V
  VCOM = 3.3V
